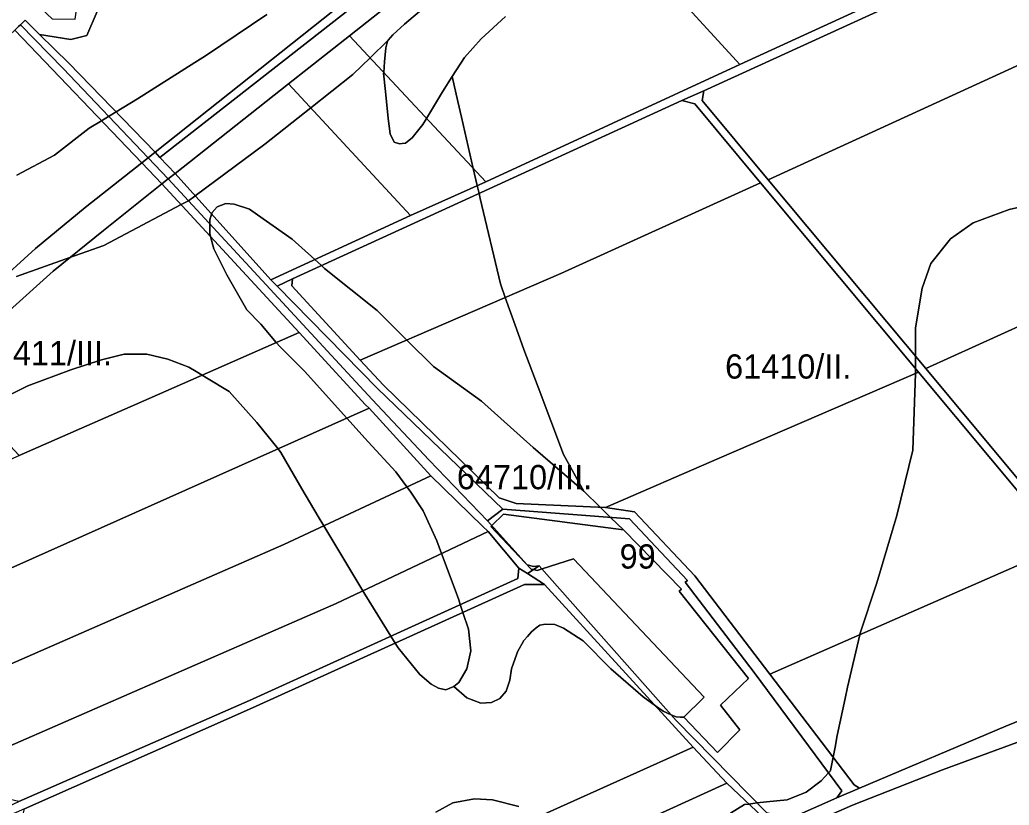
# Model space of a CAD drawing. Extents: x -522079 to -518792, y -1142400 to -1139961.
# Drawn here: x -521597 to -520985, y -1141010 to -1140524 of the extents above; entities that cross this region are included whole.
import ezdxf

# ---------------------------------------------------------------- set-up
doc = ezdxf.new("R2010")
doc.units = 0
for name, color, linetype in [('Hranice parcel', 7, 'Continuous'), ('Parcelní čísla', 7, 'Continuous'), ('Poz předměty', 7, 'Continuous'), ('Vnitřní kresba', 7, 'Continuous'), ('Značky bodu BP', 7, 'Continuous'), ('Značky budov', 7, 'Continuous')]:
    doc.layers.add(name, color=color, linetype=linetype)

msp = doc.modelspace()

# ---------------------------------------------------------------- linework, layer by layer
at = {"layer": 'Hranice parcel'}
for points in [[(-521245.45, -1140392.88), (-521233.39, -1140383.74), (-521212.85, -1140368.17), (-521190.73, -1140351.49), (-521181.05, -1140344.19), (-521160.13, -1140329.24), (-521148.51, -1140320.94), (-521130.86, -1140309.33), (-521127.62, -1140312.94), (-521177.32, -1140348.18), (-521510.5, -1140608.85), (-521513.48, -1140605.69), (-521389.53, -1140507.12), (-521274.04, -1140415.55), (-521252.22, -1140398.25)], [(-521428.47, -1140683.93), (-521438.02, -1140688.47), (-521441.99, -1140684.63), (-521355.48, -1140644.9), (-521309.07, -1140623.96), (-521152, -1140551.52), (-521060.49, -1140509.3), (-521045.09, -1140502.65), (-521031.07, -1140496.4), (-520906.37, -1140439.12), (-520903.84, -1140443.54), (-521038.29, -1140505.39), (-521174.07, -1140567.72), (-521187.8, -1140573.75), (-521306.81, -1140628.37)], [(-521521.75, -1140612.22), (-521517.85, -1140609.14), (-521505.44, -1140622.18), (-521509.24, -1140625.15)], [(-521283.37, -1140860.94), (-521279.53, -1140861.89), (-521275.9, -1140861.47), (-521283.24, -1140866.3), (-521288.46, -1140863.02), (-521307.59, -1140840.17), (-521311.05, -1140836.96), (-521343.03, -1140805.79), (-521381.12, -1140763.92), (-521383.31, -1140761.88), (-521424.45, -1140717.21), (-521509.24, -1140625.15), (-521505.44, -1140622.18), (-521379.23, -1140758.51), (-521344.11, -1140796.22), (-521307.86, -1140833.61)], [(-521077.97, -1140999.02), (-521091.97, -1141005.03), (-521088.9, -1141000.66), (-521143.12, -1140927.46), (-521185.72, -1140871.68), (-521184.18, -1140870.5), (-521220.23, -1140832.37), (-521298.55, -1140826.47), (-521375.87, -1140751.79), (-521438.02, -1140688.47), (-521428.47, -1140683.93), (-521428.9, -1140688.4), (-521386.59, -1140734.32), (-521372.2, -1140749.84), (-521300.72, -1140819.47), (-521290.3, -1140823.03), (-521234.98, -1140825.42), (-521217.11, -1140828.01), (-521179.82, -1140867.68), (-521133.42, -1140928.49), (-521081.12, -1140996.97)], [(-521134.18, -1141024.63), (-521134.23, -1141020.21), (-521160.03, -1140995.91), (-521180.73, -1140973.62), (-521272.67, -1140872.95), (-521283.24, -1140866.3), (-521275.9, -1140861.47), (-521191.17, -1140957.11), (-521135.25, -1141014.2), (-521120.79, -1141017.67)]]:
    msp.add_lwpolyline(points, close=True, dxfattribs=at)
for points in [[(-521120.79, -1141017.67), (-521091.97, -1141005.03), (-521077.97, -1140999.02), (-520987.34, -1140960.66), (-520896.33, -1140923.45)], [(-520970.5, -1140967.09), (-521026.59, -1140987.63), (-521082.18, -1141009.47), (-521112.83, -1141022.98)]]:
    msp.add_lwpolyline(points, dxfattribs=at)
at = {"layer": 'Parcelní čísla'}
for points in [[(-521042, -1140261.25), (-521029.36, -1140265.01), (-521071.25, -1140292.13), (-521105.44, -1140313.39), (-521138.04, -1140336), (-521166.55, -1140356.84), (-521170.88, -1140360.01), (-521186.8, -1140371.65), (-521202.24, -1140382.94), (-521262.52, -1140430.5), (-521393.25, -1140533.65), (-521431, -1140563.44), (-521501.14, -1140618.78), (-521510.5, -1140608.85), (-521177.32, -1140348.18), (-521127.62, -1140312.94), (-521125.23, -1140315.3), (-521106.97, -1140303.78), (-521080.73, -1140284.42), (-521065.28, -1140272.43), (-521054.61, -1140266.48)], [(-521060.49, -1140509.3), (-521152, -1140551.52), (-521262.52, -1140430.5), (-521202.24, -1140382.94), (-521186.8, -1140371.65)], [(-521309.07, -1140623.96), (-521393.25, -1140533.65), (-521262.52, -1140430.5), (-521152, -1140551.52)], [(-521174.07, -1140567.72), (-521038.29, -1140505.39), (-520903.84, -1140443.54), (-520902.4, -1140445.74), (-520890.58, -1140462.46), (-520871.65, -1140486.28), (-520862.22, -1140497.87), (-521134.28, -1140622.71), (-521175.11, -1140573.76)], [(-520862.22, -1140497.87), (-520765.71, -1140616.57), (-520897.82, -1140676.39), (-521036.95, -1140739.4), (-521134.28, -1140622.71)], [(-521521.75, -1140612.22), (-521600.31, -1140530.11), (-521598.04, -1140528.01), (-521596.8, -1140526.87), (-521570.34, -1140553.98), (-521517.85, -1140609.14)], [(-521587.52, -1140665.2), (-521613.36, -1140688.64), (-521670.89, -1140604.59), (-521650.96, -1140608.19), (-521643.99, -1140618.34), (-521635.78, -1140620.38), (-521621.47, -1140616.67), (-521618.3, -1140572.85), (-521633.5, -1140565.29), (-521616.47, -1140556.14), (-521611.96, -1140540.86), (-521600.31, -1140530.11), (-521521.75, -1140612.22), (-521556.8, -1140639.91)], [(-521309.07, -1140623.96), (-521355.48, -1140644.9), (-521431, -1140563.44), (-521393.25, -1140533.65)], [(-521431, -1140563.44), (-521355.48, -1140644.9), (-521441.99, -1140684.63), (-521501.14, -1140618.78)], [(-521187.8, -1140573.75), (-521174.07, -1140567.72), (-521175.11, -1140573.76), (-521134.28, -1140622.71), (-521036.95, -1140739.4), (-520947.33, -1140846.85), (-520890.08, -1140915.49), (-520882.47, -1140917.37), (-520896.33, -1140923.45), (-520894.6, -1140917.89), (-520952.05, -1140848.96), (-521041.47, -1140741.65), (-521139.09, -1140624.65), (-521179.71, -1140575.8)], [(-521428.47, -1140683.93), (-521306.81, -1140628.37), (-521187.8, -1140573.75), (-521179.71, -1140575.8), (-521139.09, -1140624.65), (-521262.57, -1140680.65), (-521386.59, -1140734.32), (-521428.9, -1140688.4)], [(-521036.95, -1140739.4), (-520897.82, -1140676.39), (-520765.71, -1140616.57), (-520757.18, -1140627.06), (-520745.42, -1140642.26), (-520733.42, -1140657.97), (-520724.12, -1140671.61), (-520771, -1140692.05), (-520722.34, -1140745.4), (-520809.38, -1140784.65), (-520947.33, -1140846.85)], [(-521424.45, -1140717.21), (-521517.19, -1140758), (-521597.52, -1140793.25), (-521643.56, -1140744), (-521605.53, -1140705.44), (-521576.52, -1140679.31), (-521545.43, -1140654.05), (-521509.24, -1140625.15)], [(-521386.59, -1140734.32), (-521262.57, -1140680.65), (-521139.09, -1140624.65), (-521041.47, -1140741.65), (-521164.66, -1140794.98), (-521234.98, -1140825.42), (-521290.3, -1140823.03), (-521300.72, -1140819.47), (-521372.2, -1140749.84)], [(-521589.34, -1140856.91), (-521690.16, -1140901.59), (-521731.35, -1140851.98), (-521597.52, -1140793.25), (-521517.19, -1140758), (-521424.45, -1140717.21), (-521383.31, -1140761.88), (-521381.12, -1140763.92), (-521473.38, -1140805.12)], [(-521234.98, -1140825.42), (-521164.66, -1140794.98), (-521041.47, -1140741.65), (-520952.05, -1140848.96), (-521133.42, -1140928.49), (-521179.82, -1140867.68), (-521217.11, -1140828.01)], [(-521589.34, -1140856.91), (-521473.38, -1140805.12), (-521381.12, -1140763.92), (-521343.03, -1140805.79), (-521433.97, -1140848.31), (-521555.85, -1140901.74), (-521654.5, -1140944.84), (-521662.84, -1140934.49), (-521690.16, -1140901.59)], [(-521343.03, -1140805.79), (-521311.05, -1140836.96), (-521307.59, -1140840.17), (-521401.58, -1140884.75), (-521526.28, -1140939.14), (-521624.6, -1140981.98), (-521654.5, -1140944.84), (-521555.85, -1140901.74), (-521433.97, -1140848.31)], [(-521526.28, -1140939.14), (-521401.58, -1140884.75), (-521307.59, -1140840.17), (-521288.46, -1140863.02), (-521289.17, -1140869.28), (-521455.15, -1140944.86), (-521597.65, -1141007.23), (-521605.69, -1141005.48), (-521624.6, -1140981.98)], [(-521133.42, -1140928.49), (-520952.05, -1140848.96), (-520894.6, -1140917.89), (-520896.33, -1140923.45), (-520987.34, -1140960.66), (-521077.97, -1140999.02), (-521081.12, -1140996.97)], [(-521288.46, -1140863.02), (-521283.24, -1140866.3), (-521272.67, -1140872.95), (-521285.04, -1140873.12), (-521453.3, -1140949.4), (-521594.31, -1141011.83), (-521607.81, -1141017.81), (-521735.67, -1141074.42), (-521844.44, -1141121.41), (-521845.59, -1141127.96), (-521855.85, -1141115.33), (-521847.83, -1141117.27), (-521813.35, -1141102.46), (-521737.51, -1141069.87), (-521612.22, -1141013.76), (-521597.65, -1141007.23), (-521455.15, -1140944.86), (-521289.17, -1140869.28)], [(-521453.3, -1140949.4), (-521285.04, -1140873.12), (-521272.67, -1140872.95), (-521180.73, -1140973.62), (-521309.93, -1141031.69), (-521313.87, -1141033.11), (-521404.59, -1141074.2), (-521511.15, -1141120.5), (-521541.57, -1141083.01), (-521595.68, -1141017.57), (-521594.31, -1141011.83)], [(-520895.4, -1141219.71), (-520895.96, -1141221.04), (-521038.45, -1141284.46), (-521072.62, -1141164.33), (-521112.83, -1141022.98), (-521082.18, -1141009.47), (-521026.59, -1140987.63), (-520970.5, -1140967.09), (-520964.29, -1140970.32), (-520927.66, -1141102.94)], [(-521296.08, -1141050.04), (-521285.67, -1141044.64), (-521289.36, -1141034.73), (-521302.83, -1141040.76), (-521309.93, -1141031.69), (-521180.73, -1140973.62), (-521160.03, -1140995.91), (-521291.39, -1141055.81)], [(-521134.18, -1141024.63), (-521223.67, -1141064.26), (-521262.72, -1141081.47), (-521271.3, -1141080.74), (-521291.39, -1141055.81), (-521160.03, -1140995.91), (-521134.23, -1141020.21)]]:
    msp.add_lwpolyline(points, close=True, dxfattribs=at)
msp.add_lwpolyline([(-521613.36, -1140688.64), (-521587.52, -1140665.2), (-521556.8, -1140639.91), (-521521.75, -1140612.22), (-521509.24, -1140625.15), (-521545.43, -1140654.05), (-521576.52, -1140679.31), (-521605.53, -1140705.44)], dxfattribs=at)
at = {"layer": 'Poz předměty'}
msp.add_lwpolyline([(-521389.53, -1140507.12), (-521513.48, -1140605.69), (-521566.82, -1140550.59), (-521584.91, -1140532.83), (-521565.66, -1140535.94), (-521555.6, -1140533.49), (-521549.24, -1140518.67), (-521549.91, -1140499.85), (-521541.79, -1140492.15), (-521495.23, -1140479.84), (-521471.95, -1140488.22), (-521462.16, -1140502.96), (-521450.52, -1140503.04), (-521437.98, -1140472.83), (-521435.8, -1140458.35)], close=True, dxfattribs=at)
at = {"layer": 'Vnitřní kresba'}
msp.add_lwpolyline([(-521606.9, -1140511.13), (-521592.51, -1140508.64), (-521577.07, -1140523.11), (-521562.91, -1140523.45), (-521557.78, -1140487.71), (-521540.23, -1140479.04), (-521496.06, -1140465.78), (-521465.61, -1140476.61), (-521468.11, -1140480.32), (-521471.95, -1140488.22), (-521495.23, -1140479.84), (-521541.79, -1140492.15), (-521549.91, -1140499.85), (-521549.24, -1140518.67), (-521555.6, -1140533.49), (-521565.66, -1140535.94), (-521584.91, -1140532.83), (-521593.79, -1140524.1), (-521596.8, -1140526.87), (-521598.04, -1140528.01)], dxfattribs=at)
for points in [[(-521513.48, -1140605.69), (-521517.85, -1140609.14), (-521570.34, -1140553.98), (-521596.8, -1140526.87), (-521593.79, -1140524.1), (-521584.91, -1140532.83), (-521566.82, -1140550.59)], [(-521517.85, -1140609.14), (-521513.48, -1140605.69), (-521510.5, -1140608.85), (-521501.14, -1140618.78), (-521505.44, -1140622.18)], [(-521501.14, -1140618.78), (-521441.99, -1140684.63), (-521438.02, -1140688.47), (-521375.87, -1140751.79), (-521298.55, -1140826.47), (-521307.86, -1140833.61), (-521344.11, -1140796.22), (-521379.23, -1140758.51), (-521505.44, -1140622.18)]]:
    msp.add_lwpolyline(points, close=True, dxfattribs=at)
at = {"layer": 'Značky bodu BP'}
for points in [[(-521314.13, -1140488.23), (-521359.2, -1140526.55), (-521366.49, -1140533.05), (-521369.36, -1140536.45), (-521369.47, -1140536.57), (-521380.52, -1140547.3), (-521391.21, -1140557.67), (-521417.24, -1140578.28), (-521445.69, -1140600.79), (-521488.72, -1140632.6), (-521488.95, -1140632.77), (-521492.92, -1140635.7), (-521493.16, -1140635.88), (-521497.32, -1140638.09), (-521545.14, -1140663.46), (-521566.13, -1140670.87), (-521599.12, -1140682.51)], [(-521296.83, -1140521.82), (-521311.93, -1140535.49), (-521322.2, -1140547.14), (-521329.76, -1140558.79), (-521335.7, -1140568.27), (-521341.35, -1140577.71), (-521345.58, -1140584.79), (-521347.86, -1140588.59), (-521354.61, -1140596.72), (-521356.45, -1140598.2), (-521358.66, -1140599.98), (-521360.65, -1140600.26), (-521362.44, -1140600.51), (-521365.68, -1140599.43), (-521368.11, -1140594.28), (-521369.46, -1140584.8), (-521371.09, -1140568.03), (-521372.17, -1140556.89), (-521372.12, -1140556.32), (-521371.55, -1140549.74), (-521370.81, -1140541.18), (-521370.09, -1140538.7), (-521369.47, -1140536.57), (-521369.36, -1140536.45), (-521366.49, -1140533.05), (-521359.2, -1140526.55), (-521314.13, -1140488.23)], [(-521444.35, -1140520.43), (-521482.31, -1140546.07), (-521488.93, -1140550.27), (-521524.31, -1140572.72), (-521537.62, -1140580.75), (-521542.22, -1140583.53), (-521546.64, -1140586.2), (-521554.17, -1140590.74), (-521575.67, -1140607.49), (-521598.95, -1140619.93)], [(-521598.95, -1140619.93), (-521575.67, -1140607.49), (-521554.17, -1140590.74), (-521546.64, -1140586.2), (-521542.22, -1140583.53), (-521537.62, -1140580.75), (-521524.31, -1140572.72), (-521488.93, -1140550.27), (-521482.31, -1140546.07), (-521444.35, -1140520.43)], [(-521617.61, -1140762.73), (-521592.12, -1140750.19), (-521565.63, -1140740.17), (-521546.64, -1140734.15), (-521532.65, -1140730.64), (-521518.65, -1140730.64), (-521505.66, -1140733.65), (-521492.66, -1140738.66), (-521488.19, -1140741.31), (-521484.39, -1140743.57), (-521481.67, -1140745.18), (-521467.68, -1140753.7), (-521450.68, -1140772.76), (-521437.48, -1140789.09), (-521435.69, -1140791.31), (-521422.65, -1140813.77), (-521412.7, -1140830.91), (-521409.2, -1140836.73), (-521385.01, -1140876.89), (-521384.36, -1140877.96), (-521383.71, -1140879.04), (-521367.63, -1140905.01), (-521364.95, -1140909.34), (-521363.22, -1140912.13), (-521349.73, -1140928.68), (-521342.73, -1140934.69), (-521338.23, -1140937.2), (-521333.73, -1140938.2), (-521328.74, -1140936.19), (-521320.79, -1140943.14), (-521312.14, -1140946.39), (-521305.48, -1140946.03), (-521300.25, -1140943.5), (-521296.46, -1140938.98), (-521294.12, -1140932.29), (-521293.04, -1140925.24), (-521289.8, -1140915.81), (-521289.44, -1140914.76), (-521285.47, -1140907.71), (-521283.3, -1140905.19), (-521280.79, -1140902.28), (-521277.8, -1140899.91), (-521275.56, -1140898.13), (-521273.3, -1140897.78), (-521271.96, -1140897.58), (-521266.37, -1140897.76), (-521260.96, -1140900.11), (-521248.71, -1140907.89), (-521231.59, -1140925.24), (-521211.59, -1140942.6), (-521204.15, -1140947.97), (-521199.33, -1140951.45), (-521194.28, -1140953.59), (-521191.22, -1140954.89), (-521188.61, -1140954.99), (-521186.59, -1140955.07), (-521165.77, -1140976.98), (-521151.91, -1140962.84), (-521163.92, -1140947.73), (-521146.54, -1140931.11), (-521189.38, -1140877.12), (-521187.89, -1140875.92), (-521223.91, -1140839.29), (-521231.85, -1140831.49), (-521238.18, -1140825.28), (-521248.27, -1140815.37), (-521260.91, -1140792.54), (-521276.65, -1140750.96), (-521285.44, -1140727.74), (-521290, -1140714.96), (-521296.94, -1140695.52), (-521299.96, -1140687.05), (-521312.48, -1140634.31), (-521313.18, -1140631.27), (-521314.31, -1140626.33), (-521316.74, -1140615.73), (-521324, -1140584.08), (-521326.22, -1140574.33), (-521329.76, -1140558.79), (-521322.2, -1140547.14), (-521311.93, -1140535.49), (-521296.83, -1140521.82)], [(-521599.12, -1140682.51), (-521566.13, -1140670.87), (-521545.14, -1140663.46), (-521497.32, -1140638.09), (-521493.16, -1140635.88), (-521492.92, -1140635.7), (-521488.95, -1140632.77), (-521488.72, -1140632.6), (-521445.69, -1140600.79), (-521417.24, -1140578.28), (-521391.21, -1140557.67), (-521380.52, -1140547.3), (-521369.47, -1140536.57), (-521370.09, -1140538.7), (-521370.81, -1140541.18), (-521371.55, -1140549.74), (-521372.12, -1140556.32), (-521372.17, -1140556.89), (-521371.09, -1140568.03), (-521369.46, -1140584.8), (-521368.11, -1140594.28), (-521365.68, -1140599.43), (-521362.44, -1140600.51), (-521360.65, -1140600.26), (-521358.66, -1140599.98), (-521356.45, -1140598.2), (-521354.61, -1140596.72), (-521347.86, -1140588.59), (-521345.58, -1140584.79), (-521341.35, -1140577.71), (-521335.7, -1140568.27), (-521329.76, -1140558.79), (-521326.22, -1140574.33), (-521324, -1140584.08), (-521316.74, -1140615.73), (-521314.31, -1140626.33), (-521313.18, -1140631.27), (-521312.48, -1140634.31), (-521299.96, -1140687.05), (-521296.94, -1140695.52), (-521290, -1140714.96), (-521285.44, -1140727.74), (-521276.65, -1140750.96), (-521260.91, -1140792.54), (-521248.27, -1140815.37), (-521279.76, -1140788.29), (-521311.74, -1140759.72), (-521341.23, -1140738.16), (-521357.74, -1140721.83), (-521376.21, -1140703.57), (-521408.7, -1140677.5), (-521410.61, -1140675.77), (-521414.69, -1140672.09), (-521428.69, -1140659.45), (-521446.68, -1140646.92), (-521455.18, -1140640.9), (-521464.68, -1140637.89), (-521469.67, -1140637.39), (-521472.48, -1140638.41), (-521475.17, -1140639.39), (-521478.17, -1140642.91), (-521478.52, -1140643.96), (-521479.67, -1140647.42), (-521479.67, -1140650.01), (-521479.67, -1140655.94), (-521479.19, -1140657.78), (-521477.17, -1140665.46), (-521469.17, -1140681.51), (-521456.68, -1140703.07), (-521448.18, -1140712.09), (-521438.52, -1140723.4), (-521436.19, -1140726.13), (-521421.19, -1140741.17), (-521394.99, -1140770.11), (-521381.71, -1140784.79), (-521364.72, -1140803.34), (-521357.74, -1140812.67), (-521355.72, -1140815.37), (-521347.73, -1140827.4), (-521339.23, -1140845.95), (-521336.34, -1140853.8), (-521328.03, -1140876.34), (-521325.74, -1140882.55), (-521324.76, -1140885.49), (-521323.13, -1140890.39), (-521319.74, -1140900.6), (-521318.24, -1140914.13), (-521320.74, -1140925.17), (-521325.74, -1140933.69), (-521328.74, -1140936.19), (-521333.73, -1140938.2), (-521338.23, -1140937.2), (-521342.73, -1140934.69), (-521349.73, -1140928.68), (-521363.22, -1140912.13), (-521364.95, -1140909.34), (-521367.63, -1140905.01), (-521383.71, -1140879.04), (-521384.36, -1140877.96), (-521385.01, -1140876.89), (-521409.2, -1140836.73), (-521412.7, -1140830.91), (-521422.65, -1140813.77), (-521435.69, -1140791.31), (-521437.48, -1140789.09), (-521450.68, -1140772.76), (-521467.68, -1140753.7), (-521481.67, -1140745.18), (-521484.39, -1140743.57), (-521488.19, -1140741.31), (-521492.66, -1140738.66), (-521505.66, -1140733.65), (-521518.65, -1140730.64), (-521532.65, -1140730.64), (-521546.64, -1140734.15), (-521565.63, -1140740.17), (-521592.12, -1140750.19), (-521617.61, -1140762.73)], [(-520962.58, -1140635.86), (-520985.36, -1140641.14), (-521007.56, -1140649.34), (-521021.58, -1140659.31), (-521033.84, -1140674.54), (-521039.1, -1140689.78), (-521043.19, -1140714.39), (-521043.19, -1140731.92), (-521043.19, -1140739.59), (-521043.29, -1140742.44), (-521044.94, -1140789.98), (-521054.87, -1140830.42), (-521067.14, -1140872.02), (-521077.66, -1140903.67), (-521077.75, -1140904.08), (-521085.25, -1140936.48), (-521086.78, -1140943.6), (-521091.68, -1140966.37), (-521093.05, -1140973.64), (-521094.21, -1140979.83), (-521095.76, -1140988.05), (-521096.08, -1140988.39), (-521097.13, -1140989.55), (-521101.61, -1140994.5), (-521110.95, -1141001.53), (-521122.64, -1141006.22), (-521135.49, -1141007.39), (-521141.19, -1141008.13), (-521143.95, -1141008.5), (-521146.33, -1141008.81), (-521148.92, -1141009.15), (-521157.69, -1141014.42)], [(-521157.69, -1141014.42), (-521148.92, -1141009.15), (-521146.33, -1141008.81), (-521143.95, -1141008.5), (-521141.19, -1141008.13), (-521135.49, -1141007.39), (-521122.64, -1141006.22), (-521110.95, -1141001.53), (-521101.61, -1140994.5), (-521097.13, -1140989.55), (-521096.08, -1140988.39), (-521095.76, -1140988.05), (-521094.21, -1140979.83), (-521093.05, -1140973.64), (-521091.68, -1140966.37), (-521086.78, -1140943.6), (-521085.25, -1140936.48), (-521077.75, -1140904.08), (-521077.66, -1140903.67), (-521067.14, -1140872.02), (-521054.87, -1140830.42), (-521044.94, -1140789.98), (-521043.29, -1140742.44), (-521043.19, -1140739.59), (-521043.19, -1140731.92), (-521043.19, -1140714.39), (-521039.1, -1140689.78), (-521033.84, -1140674.54), (-521021.58, -1140659.31), (-521007.56, -1140649.34), (-520985.36, -1140641.14), (-520962.58, -1140635.86)], [(-521288.54, -1141010.32), (-521304.89, -1141006.22), (-521315.99, -1141005.63), (-521329.43, -1141007.98), (-521339.94, -1141013.83)], [(-521339.94, -1141013.83), (-521329.43, -1141007.98), (-521315.99, -1141005.63), (-521304.89, -1141006.22), (-521288.54, -1141010.32)]]:
    msp.add_lwpolyline(points, dxfattribs=at)
for points in [[(-521248.27, -1140815.37), (-521238.18, -1140825.28), (-521231.85, -1140831.49), (-521223.91, -1140839.29), (-521298.04, -1140829.45), (-521305.29, -1140836.48), (-521305.94, -1140837.11), (-521295.62, -1140848.04), (-521281.03, -1140863.48), (-521279.48, -1140863.83), (-521277.13, -1140864.35), (-521274.18, -1140863.41), (-521254.67, -1140857.19), (-521174.02, -1140942.81), (-521174.64, -1140943.41), (-521186.59, -1140955.07), (-521188.61, -1140954.99), (-521191.22, -1140954.89), (-521194.28, -1140953.59), (-521199.33, -1140951.45), (-521204.15, -1140947.97), (-521211.59, -1140942.6), (-521231.59, -1140925.24), (-521248.71, -1140907.89), (-521260.96, -1140900.11), (-521266.37, -1140897.76), (-521271.96, -1140897.58), (-521273.3, -1140897.78), (-521275.56, -1140898.13), (-521277.8, -1140899.91), (-521280.79, -1140902.28), (-521283.3, -1140905.19), (-521285.47, -1140907.71), (-521289.44, -1140914.76), (-521289.8, -1140915.81), (-521293.04, -1140925.24), (-521294.12, -1140932.29), (-521296.46, -1140938.98), (-521300.25, -1140943.5), (-521305.48, -1140946.03), (-521312.14, -1140946.39), (-521320.79, -1140943.14), (-521328.74, -1140936.19), (-521325.74, -1140933.69), (-521320.74, -1140925.17), (-521318.24, -1140914.13), (-521319.74, -1140900.6), (-521323.13, -1140890.39), (-521324.76, -1140885.49), (-521325.74, -1140882.55), (-521328.03, -1140876.34), (-521336.34, -1140853.8), (-521339.23, -1140845.95), (-521347.73, -1140827.4), (-521355.72, -1140815.37), (-521357.74, -1140812.67), (-521364.72, -1140803.34), (-521381.71, -1140784.79), (-521394.99, -1140770.11), (-521421.19, -1140741.17), (-521436.19, -1140726.13), (-521438.52, -1140723.4), (-521448.18, -1140712.09), (-521456.68, -1140703.07), (-521469.17, -1140681.51), (-521477.17, -1140665.46), (-521479.19, -1140657.78), (-521479.67, -1140655.94), (-521479.67, -1140650.01), (-521479.67, -1140647.42), (-521478.52, -1140643.96), (-521478.17, -1140642.91), (-521475.17, -1140639.39), (-521472.48, -1140638.41), (-521469.67, -1140637.39), (-521464.68, -1140637.89), (-521455.18, -1140640.9), (-521446.68, -1140646.92), (-521428.69, -1140659.45), (-521414.69, -1140672.09), (-521410.61, -1140675.77), (-521408.7, -1140677.5), (-521376.21, -1140703.57), (-521357.74, -1140721.83), (-521341.23, -1140738.16), (-521311.74, -1140759.72), (-521279.76, -1140788.29)], [(-521223.91, -1140839.29), (-521187.89, -1140875.92), (-521189.38, -1140877.12), (-521146.54, -1140931.11), (-521163.92, -1140947.73), (-521151.91, -1140962.84), (-521165.77, -1140976.98), (-521186.59, -1140955.07), (-521174.64, -1140943.41), (-521174.02, -1140942.81), (-521254.67, -1140857.19), (-521274.18, -1140863.41), (-521277.13, -1140864.35), (-521279.48, -1140863.83), (-521281.03, -1140863.48), (-521295.62, -1140848.04), (-521305.94, -1140837.11), (-521305.29, -1140836.48), (-521298.04, -1140829.45)]]:
    msp.add_lwpolyline(points, close=True, dxfattribs=at)
at = {"layer": 'Značky budov'}
msp.add_lwpolyline([(-521283.37, -1140860.94), (-521307.86, -1140833.61), (-521298.55, -1140826.47), (-521220.23, -1140832.37), (-521184.18, -1140870.5), (-521185.72, -1140871.68), (-521143.12, -1140927.46), (-521088.9, -1141000.66), (-521091.97, -1141005.03), (-521120.79, -1141017.67), (-521135.25, -1141014.2), (-521191.17, -1140957.11), (-521275.9, -1140861.47), (-521279.53, -1140861.89)], close=True, dxfattribs=at)

# ---------------------------------------------------------------- texts
at = {"layer": 'Značky bodu BP'}
for s, rotation, p in [('62411/III.', 0, (-521623.72, -1140737.38)), ('61410/II.', 0, (-521161.02, -1140745.69)), ('64710/III.', 0, (-521326.85, -1140814.12)), ('99', 360, (-521226.24, -1140863.18))]:
    msp.add_text(s, height=15, rotation=rotation, dxfattribs=at).set_placement(p)

doc.saveas('drawing.dxf')
